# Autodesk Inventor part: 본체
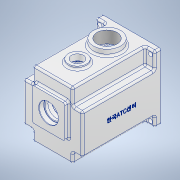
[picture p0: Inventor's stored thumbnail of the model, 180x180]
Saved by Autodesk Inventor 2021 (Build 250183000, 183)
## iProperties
Created: 2022-08
Part Number: 본체
Material: 알루미늄 6061
Document SubType Name: Modeling
Designer: Owner
Density: 2.7 g/cm^3
Appearance: 알루미늄 - 평지
Mass: 1405.03 g
Surface Area: 1171.05 cm^2
Volume: 520.382 cm^3
Author: Owner
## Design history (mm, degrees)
sketch "스케치1"
  geometry: L1 (-49, 55)-(49, 55); L2 (49, 55)-(49, -55); L3 (49, -55)-(-49, -55); L4 (-49, -55)-(-49, 55); L5 (-49, 55)-(49, -55); L6 (49, 55)-(-49, -55); 1 further point
  constraints: 12 end point, 2 midpoint, 2 parallel, 1 horizontal, 1 perpendicular
  dimensions: "d0" = 98 distance of L2.end L3.end; "d1" = 110 distance of L1.end L2.end
extrude "돌출1" new body sketch "스케치1" distance "d2" = 130; taper "d3" = 0 deg
sketch "스케치2"
  geometry: L1 (49, -55)-(49, 55) reference; L2 (49, 55)-(33, 55); L3 (33, 55)-(33, 28); L4 (33, 28)-(49, 28); L5 (49, 28)-(49, 55); L6 (49, 55)-(-49, 55) reference; L7 (-49, 55)-(-33, 55); L8 (-33, 55)-(-33, 28); L9 (-33, 28)-(-49, 28); L10 (-49, 28)-(-49, 55); L11 (-49, -55)-(49, -55) reference; L12 (-49, -55)-(-33, -55); L13 (-33, -55)-(-33, -38); L14 (-33, -38)-(-49, -38); L15 (-49, -38)-(-49, -55); L16 (49, -55)-(33, -55); L17 (33, -55)-(33, -38); L18 (33, -38)-(49, -38); L19 (49, -38)-(49, -55); 6 further points
  constraints: 32 end point, 8 parallel, 4 horizontal, 4 perpendicular
  dimensions: "d4" = 16 distance of L4.end L3.end; "d5" = 27 distance of L3.end L2.end; "d6" = 16 distance of L8.end L9.end; "d7" = 27 distance of L7.end L8.end; "d8" = 16 distance of L14.end L13.end; "d9" = 17 distance of L13.end L12.end; "d10" = 16 distance of L17.end L18.end; "d11" = 17 distance of L16.end L17.end
extrude "돌출2" cut sketch "스케치2" distance "d12" = 120; taper "d13" = 0 deg
sketch "스케치3"
  geometry: L1 (-27, 33)-(27, 33); L2 (27, 33)-(27, -21); L3 (27, -21)-(-27, -21); L4 (-27, -21)-(-27, 33); L5 (-27, 33)-(27, -21); L6 (27, 33)-(-27, -21); L7 (-33, -55)-(33, -55) reference; 3 further points
  constraints: 12 end point, 3 midpoint, 2 parallel, 1 horizontal, 1 perpendicular, 1 vertical alignment
  dimensions: "d149" = 54 distance of L2.end L3.end; "d150" = 54 distance of L1.end L2.end; "d151" = 61 distance from line of L7 point (0, 6)
extrude "돌출3" join sketch "스케치3" distance "d16" = 7; taper "d17" = 0 deg
sketch "스케치4"
  geometry: L1 (98, 0)-(0, 0) reference; C1 r 15 at (49, -89); C2 r 22.5 at (49, -40); 3 further points
  constraints: 2 centre point, 2 midpoint, 2 vertical alignment
  dimensions: "d18" = 30 diameter of C1; "d19" = 45 diameter of C2; "d20" = 40 distance of C2.centre point (49, 0); "d21" = 49 distance of C1.centre C2.centre
extrude "돌출4" join sketch "스케치4" distance "d22" = 5; taper "d23" = 0 deg
extrude "돌출5" join sketch "스케치4" distance "d24" = 10; taper "d25" = 0 deg
sketch "스케치5"
  geometry: L1 (49, -55)-(-49, -55) reference; L2 (-23, 30.143)-(-23, 45); L3 (-23, 45)-(23, 45); L4 (23, 45)-(23, 30.143); L5 (26, 31.729)-(26, 48); L6 (26, 48)-(-26, 48); L7 (-26, 48)-(-26, 31.729); A1 r 42 centre (0, -5) between (-23, 30.143) and (23, 30.143); A2 r 45 centre (0, -5) between (-26, 31.729) and (26, 31.729); 1 further point
  constraints: 12 end point, 4 perpendicular, 4 point on circle, 2 centre point, 1 vertical, 1 vertical alignment, 3 other
  dimensions: "d32" = 84 diameter of A1; "d33" = 50 distance from line of L1 A1.centre; "d34" = 50 distance from line of A1.centre L3; "d35" = 46 distance between parallel lines of L4 L2; "d36" = 23 distance from line of A1.centre L4; "d39" = 3 radial gap between concentric circles of A1 A2
extrude "돌출8" cut sketch "스케치5" distance "d40" = 9; taper "d41" = 0 deg
sketch "스케치6"
  geometry: L1 (23, 30.143)-(23, 45) reference; L2 (23, 45)-(-23, 45) reference; L3 (-23, 45)-(-23, 30.143) reference; L4 (49, -55)-(-49, -55) reference; L5 (-35.778, -1.006)-(-41.81, -1.006); L6 (-35.778, -8.994)-(-41.81, -8.994); L7 (41.81, -1.006)-(35.778, -1.006); L8 (41.81, -8.994)-(35.778, -8.994); L9 (-40, -5)-(40, -5); A1 r 42 centre (0, -5) between (-23, 30.143) and (23, 30.143) reference; A2 r 36 centre (0, -5) between (36, -5) and (-36, -5); A3 r 4 centre (36, -5) between (35.778, -1.006) and (35.778, -8.994); A4 r 4 centre (-36, -5) between (-35.778, -8.994) and (-35.778, -1.006); 1 further point
  constraints: 16 point on circle, 12 end point, 5 horizontal, 3 centre point, 2 point on line, 1 coincident, 1 midpoint
  dimensions: "d43" = 72 diameter of A2; "d46" = 4 radius of A3; "d47" = 4 radius of A4
extrude "돌출9" cut sketch "스케치6" distance "d48" = 114; taper "d49" = 0 deg
sketch "스케치7"
  geometry: L1 (-35.778, -1.006)-(-41.81, -1.006) reference; L2 (-41.81, -8.994)-(-35.778, -8.994) reference; L3 (35.778, -8.994)-(41.81, -8.994) reference; L4 (41.81, -1.006)-(35.778, -1.006) reference; L5 (23, 45)-(23, 30.143) reference; L6 (-23, 45)-(23, 45) reference; L7 (-23, 30.143)-(-23, 45) reference; A1 r 42 centre (0, -5) between (-23, 30.143) and (-41.81, -1.006) reference; A2 r 4 centre (-36, -5) between (-35.778, -8.994) and (-35.778, -1.006) reference; A3 r 42 centre (0, -5) between (-41.81, -8.994) and (41.81, -8.994) reference; A4 r 4 centre (36, -5) between (35.778, -1.006) and (35.778, -8.994) reference; A5 r 42 centre (0, -5) between (41.81, -1.006) and (23, 30.143) reference; A6 r 21 centre (0, 6) between (8.978, -12.984) and (-8.978, -12.984); A7 r 15 centre (0, -25) between (-8.978, -12.984) and (8.978, -12.984); 1 further point
  constraints: 4 point on circle, 2 centre point, 2 vertical alignment
  dimensions: "d50" = 30 diameter of A7; "d51" = 42 diameter of A6; "d52" = 20 distance of A7.centre A1.centre; "d53" = 11 distance of A1.centre A6.centre
extrude "돌출10" cut sketch "스케치7" distance "d54" = 7; taper "d55" = 0 deg
sketch "스케치8"
  geometry: A1 r 21 centre (0, 6) between (8.978, -12.984) and (-8.978, -12.984) reference; 2 further points
  constraints: 1 coincident
hole "구멍1" sketch "스케치8" at (0, 6) diameter "d56" = 28; stored, may be unused: countersink angle "d60" = 90 deg, drill point angle "d62" = 118 deg; dims "d57" = 6, "d58" = 35, "d59" = 10, "d61" = 8
sketch "스케치10"
  geometry: A1 r 15 centre (0, -25) between (-8.978, -12.984) and (8.978, -12.984) reference; 2 further points
  constraints: 1 coincident
hole "구멍3" sketch "스케치10" at (0, -25) diameter "d70" = 19; stored, may be unused: countersink angle "d74" = 90 deg, drill point angle "d76" = 0 deg; dims "d71" = 6, "d72" = 22, "d73" = 7, "d75" = 10
sketch "스케치11"
  geometry: C1 r 22.5 at (0, 0) reference; 2 further points
  constraints: 1 coincident
hole "구멍4" sketch "스케치11" at (0, 0) diameter "d77" = 33.376; stored, may be unused: countersink angle "d81" = 90 deg, drill point angle "d83" = 0 deg; dims "d78" = 70, "d79" = 22, "d80" = 7, "d82" = 77.3
sketch "스케치12"
  geometry: C1 r 15 at (23, 80) reference; 2 further points
  constraints: 1 coincident
hole "구멍5" sketch "스케치12" at (23, 80) diameter "d84" = 20; stored, may be unused: countersink angle "d88" = 90 deg, drill point angle "d90" = 0 deg; dims "d85" = 70, "d86" = 30, "d87" = 5, "d89" = 77.3
sketch "스케치13"
  geometry: L1 (-41.81, -8.994)-(-35.778, -8.994) reference; L2 (-35.778, -1.006)-(-41.81, -1.006) reference; L3 (35.778, -8.994)-(41.81, -8.994) reference; L4 (41.81, -1.006)-(35.778, -1.006) reference; A1 r 4 centre (-36, -5) between (-35.778, -8.994) and (-35.778, -1.006) reference; A2 r 42 centre (0, -5) between (-41.81, -1.006) and (-41.81, -8.994) reference; A3 r 42 centre (0, -5) between (41.81, -8.994) and (41.81, -1.006) reference; A4 r 4 centre (36, -5) between (35.778, -1.006) and (35.778, -8.994) reference; 1 further point
extrude "돌출11" cut sketch "스케치13" distance "d91" = 9; taper "d92" = 0 deg
sketch "스케치14"
  geometry: A1 r 45 centre (0, -5) between (-26, 31.729) and (26, 31.729) reference; 3 further points
  constraints: 2 horizontal alignment
  dimensions: "d93" = 36 distance of A1.centre point (36, -5); "d94" = 36 distance of A1.centre point (-36, -5)
hole "구멍6" sketch "스케치14" at (-36, -5), (36, -5) diameter "d95" = 3.242; stored, may be unused: countersink angle "d99" = 90 deg, drill point angle "d101" = 118 deg; dims "d96" = 7, "d97" = 30, "d98" = 5, "d100" = 9
sketch "스케치15"
  geometry: L1 (-49, -55)-(-49, 55) reference; L2 (-49, 55)-(49, 55) reference; C1 r 3.5 at (-42, 48); 1 further point
  constraints: 1 centre point
  dimensions: "d102" = 7 diameter of C1; "d103" = 7 distance from line of L1 C1.centre; "d104" = 7 distance from line of C1.centre L2
extrude "돌출12" cut sketch "스케치15" distance "d105" = 10; taper "d106" = 0 deg
fillet "모깎기1" dims "d107" = 3
fillet "모깎기2" dims "d108" = 0.3
fillet "모깎기3" dims "d112" = 0.3
fillet "모깎기4" dims "d116" = 6
chamfer "모따기3" distance "d117" = 1; stored, may be unused: second distance "d118" = 2, angle "d119" = 30 deg
chamfer "모따기4" distance "d120" = 1; stored, may be unused: second distance "d121" = 2, angle "d122" = 30 deg
fillet "모깎기5" dims "d126" = 3
fillet "모깎기6" dims "d127" = 3
fillet "모깎기7" dims "d128" = 3
fillet "모깎기8" dims "d129" = 3
fillet "모깎기9" dims "d130" = 3
fillet "모깎기10" dims "d131" = 6
fillet "모깎기11" dims "d135" = 3
fillet "모깎기12" dims "d136" = 3
fillet "모깎기13" dims "d137" = 3
fillet "모깎기14" dims "d138" = 3
fillet "모깎기15" dims "d139" = 3
fillet "모깎기16" dims "d140" = 3
fillet "모깎기17" dims "d141" = 3
fillet "모깎기18" dims "d142" = 3
fillet "모깎기19" dims "d143" = 3
fillet "모깎기20" dims "d144" = 3
fillet "모깎기21" dims "d145" = 3
fillet "모깎기22" dims "d146" = 3
fillet "모깎기23" dims "d147" = 3
fillet "모깎기24" dims "d148" = 3
fillet "모깎기25" dims "d152" = 3
fillet "모깎기26" dims "d153" = 3
sketch "스케치16"
  geometry: C1 r 14 at (0, 6) reference; 2 further points
  constraints: 1 coincident
hole "구멍7" sketch "스케치16" at (0, 6) diameter "d154" = 32; stored, may be unused: countersink angle "d158" = 90 deg, drill point angle "d160" = 0 deg; dims "d155" = 7, "d156" = 30, "d157" = 5, "d159" = 8.3
chamfer "모따기7" distance "d161" = 0.8; stored, may be unused: second distance "d162" = 2, angle "d163" = 30 deg
fillet "모깎기27" dims "d164" = 0.3
fillet "모깎기28" dims "d165" = 3
sketch "스케치17"
  geometry: L1 (0, 0)-(0, 60) reference; L2 (117, 63)-(3, 63) reference; 2 further points
  constraints: 1 other
  dimensions: "d166" = 65 distance from line of L1 point (65, 30); "d167" = 33 distance from line of L2 point (65, 30)
feature "엠보싱1" sketch "스케치17" dims "d6" = 16, "d7" = 27, "d168" = 0.5, "d169" = 0
fillet "모깎기29" dims "d173" = 3
chamfer "모따기9" distance "d174" = 1; stored, may be unused: second distance "d175" = 2, angle "d176" = 30 deg
node "솔리드1"
mirror "미러1"
mirror "미러2"
node "투영된 루프1"
node "투영된 루프2"
node "투영된 루프3"
node "투영된 루프4"
feature "A9D066F2-1C7D-4E18-AEED-F7BC21143FA4" dims "d70" = 19, "d71" = 6, "d72" = 22, "d73" = 7, "d74" = 90 deg, "d75" = 10, "d76" = 0
